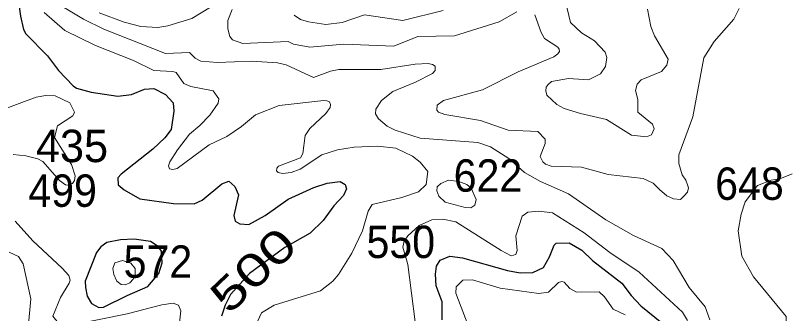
# Model space of a CAD drawing. Extents: x 499.9 to 555.3, y 9281.5 to 9336.8.
# Drawn here: x 535.43 to 539.258, y 9292.325 to 9293.797 of the extents above; entities that cross this region are included whole.
import ezdxf
from ezdxf.enums import TextEntityAlignment as Align

# ---------------------------------------------------------------- set-up
doc = ezdxf.new("R2010")
doc.units = 0
doc.header["$LTSCALE"] = 0.064
doc.layers.add('1', color=7, linetype='Continuous', lineweight=25)
doc.layers.add('2', color=7, linetype='Continuous', lineweight=13)
doc.layers.add('21', color=7, linetype='Continuous')
doc.layers.add('61', color=7, linetype='Continuous')

msp = doc.modelspace()

# ---------------------------------------------------------------- linework, layer by layer
at = {"layer": '1'}
for points in [[(535.4371, 9293.9261), (535.4546, 9293.7933), (535.4703, 9293.7273), (535.4808, 9293.7071), (535.5882, 9293.5975), (535.643, 9293.5252), (535.7149, 9293.4503), (535.7322, 9293.4378), (535.8042, 9293.4182), (535.936, 9293.3987), (536.0044, 9293.4069)], [(536.0044, 9293.4069), (536.0681, 9293.4335), (536.1149, 9293.4364), (536.1728, 9293.4068), (536.2106, 9293.3656), (536.2136, 9293.3253)], [(536.2136, 9293.3253), (536.2003, 9293.234), (536.1691, 9293.1933), (536.1103, 9293.1375), (535.9523, 9293.0129), (535.937, 9292.995), (535.9387, 9292.9606), (535.968, 9292.9357), (536.0458, 9292.8924), (536.2124, 9292.8678), (536.3131, 9292.8673), (536.3538, 9292.8846), (536.4503, 9292.965), (536.4858, 9292.9793), (536.5144, 9292.9528), (536.5333, 9292.9115), (536.5104, 9292.8092), (536.5171, 9292.7818), (536.5398, 9292.7679), (536.5836, 9292.7656), (536.665, 9292.8093), (536.7795, 9292.8896), (536.9053, 9292.9478), (536.9722, 9292.9689), (537.036, 9292.9764), (537.0605, 9292.9616), (537.0663, 9292.941), (537.0523, 9292.9084), (537.0042, 9292.8567), (536.9521, 9292.7843), (536.8869, 9292.7222), (536.7621, 9292.6508), (536.5877, 9292.523), (536.4932, 9292.4197), (536.4671, 9292.3664), (536.4487, 9292.3115)], [(537.5398, 9292.2948), (537.5408, 9292.3832), (537.511, 9292.4619), (537.5066, 9292.5203), (537.5113, 9292.5587), (537.5309, 9292.5886), (537.5781, 9292.6081), (537.6399, 9292.6011), (537.8635, 9292.5374), (537.9262, 9292.5265), (537.9879, 9292.5279), (538.0411, 9292.5527), (538.071, 9292.606), (538.0931, 9292.6624), (538.1032, 9292.6725), (538.1681, 9292.6741), (538.2311, 9292.6381), (538.2835, 9292.5863), (538.4284, 9292.4759), (538.4743, 9292.4144), (538.5232, 9292.3625), (538.6265, 9292.2787)]]:
    msp.add_lwpolyline(points, dxfattribs=at)
msp.add_lwpolyline([(536.0853, 9292.4582), (536.1398, 9292.523), (536.1553, 9292.5759), (536.152, 9292.6327), (536.1358, 9292.6561), (536.0979, 9292.6809), (536.0171, 9292.6922), (535.9503, 9292.6893), (535.882, 9292.6757), (535.8522, 9292.6549), (535.8308, 9292.6271), (535.7755, 9292.4847), (535.777, 9292.4533), (535.7846, 9292.4107), (535.806, 9292.3751), (535.8431, 9292.3549), (535.8652, 9292.3562), (535.9833, 9292.4146)], close=True, dxfattribs=at)
at = {"layer": '2'}
for points in [[(538.1747, 9293.7616), (538.1398, 9293.9095)], [(537.3081, 9293.2302), (537.269, 9293.2506), (537.2251, 9293.2866), (537.2104, 9293.3114), (537.2117, 9293.3342), (537.2401, 9293.3775), (537.296, 9293.4223), (537.409, 9293.4678), (537.4921, 9293.5109), (537.5057, 9293.526), (537.505, 9293.5466), (537.4925, 9293.5557), (537.4711, 9293.5591), (537.4067, 9293.556), (537.2363, 9293.5307), (537.0294, 9293.5307), (536.9873, 9293.5226), (536.9045, 9293.4912), (536.7683, 9293.5526), (536.7254, 9293.5625), (536.5975, 9293.572), (536.4295, 9293.5641), (536.3475, 9293.5721), (536.3187, 9293.5863), (536.2909, 9293.6149), (536.1716, 9293.609), (535.8671, 9293.7286), (535.7666, 9293.7796), (535.5814, 9293.8904)], [(535.8446, 9293.8095), (535.9686, 9293.7646), (536.0507, 9293.7425), (536.1341, 9293.7376), (536.1842, 9293.7462), (536.3021, 9293.7819), (536.4789, 9293.8914)], [(536.5011, 9293.8265), (536.4811, 9293.7724), (536.48, 9293.7311), (536.4908, 9293.6932), (536.5036, 9293.6772), (536.5544, 9293.6581), (536.778, 9293.6693), (536.8044, 9293.6559), (536.8853, 9293.6405), (537.0533, 9293.6548), (537.3016, 9293.6453), (537.4205, 9293.6933), (537.6016, 9293.6965), (537.8227, 9293.7655), (537.9095, 9293.8156)], [(537.545, 9293.8222), (537.3451, 9293.7727), (537.156, 9293.801), (537.046, 9293.7626), (536.9642, 9293.7519), (536.879, 9293.7656), (536.8402, 9293.7778), (536.8089, 9293.7987)], [(537.9985, 9293.7996), (538.0297, 9293.7131), (538.0454, 9293.6827), (538.1126, 9293.6413), (538.1186, 9293.6306), (538.1197, 9293.6191), (538.1126, 9293.6076), (538.0915, 9293.592), (537.916, 9293.5192), (537.7401, 9293.4296), (537.5463, 9293.3771), (537.5157, 9293.3546), (537.5143, 9293.3295), (537.5227, 9293.3203), (537.5539, 9293.3079), (537.7303, 9293.278), (537.8658, 9293.2315), (538.0137, 9293.2248), (538.0502, 9293.1862), (538.0499, 9293.1655), (538.0253, 9293.101), (538.0385, 9293.0738), (538.0511, 9293.0625), (538.0795, 9293.0529), (538.2294, 9293.0482), (538.3605, 9293.0122), (538.5342, 9292.9926), (538.5836, 9292.9686), (538.6149, 9292.9383), (538.6504, 9292.9072), (538.6839, 9292.8912), (538.719, 9292.8889), (538.7373, 9292.9057), (538.7535, 9292.9247), (538.7587, 9292.9461), (538.7534, 9292.9606), (538.7446, 9292.9842), (538.7275, 9293.0109), (538.7095, 9293.0668), (538.71, 9293.1088), (538.7793, 9293.2967), (538.8335, 9293.5878), (538.8848, 9293.6693), (538.9819, 9293.7791), (539.0085, 9293.8322)], [(538.5551, 9293.8276), (538.5725, 9293.7424), (538.5904, 9293.6972), (538.658, 9293.5815), (538.6518, 9293.5515), (538.6253, 9293.5202), (538.5247, 9293.4795), (538.5042, 9293.4573), (538.4967, 9293.4269), (538.5077, 9293.3829), (538.5077, 9293.3202), (538.5801, 9293.26), (538.588, 9293.2372), (538.5753, 9293.2077), (538.5499, 9293.198), (538.4763, 9293.2063), (538.3521, 9293.2841), (538.2247, 9293.3128), (538.1428, 9293.3381), (538.1077, 9293.3572), (538.0571, 9293.4039), (538.0523, 9293.4257), (538.054, 9293.443), (538.0647, 9293.4566), (538.0815, 9293.4702), (538.165, 9293.486), (538.2637, 9293.48), (538.323, 9293.5082), (538.3477, 9293.545)], [(535.5717, 9293.8125), (535.6742, 9293.7234), (535.8262, 9293.6481), (536.0136, 9293.5746), (536.1143, 9293.5248), (536.2087, 9293.5211), (536.2251, 9293.5152), (536.2623, 9293.4604), (536.2966, 9293.4459), (536.4071, 9293.4241), (536.4356, 9293.3853), (536.4331, 9293.3636), (536.3909, 9293.3053), (536.342, 9293.2532), (536.2913, 9293.2117), (536.2312, 9293.1343), (536.1936, 9293.0746), (536.1874, 9293.055), (536.1923, 9293.0405), (536.208, 9293.036), (536.2303, 9293.0411), (536.3884, 9293.1586), (536.4754, 9293.2001), (536.5473, 9293.2485), (536.6179, 9293.3069), (536.7334, 9293.3525), (536.9554, 9293.3777), (536.9697, 9293.3759), (536.9835, 9293.3711), (536.9875, 9293.3567), (536.9866, 9293.3423), (536.9655, 9293.3132), (536.8865, 9293.2387), (536.862, 9293.2049), (536.8518, 9293.1155), (536.8391, 9293.0942), (536.7309, 9293.0523), (536.7221, 9293.0433)], [(538.3477, 9293.545), (538.354, 9293.5892), (538.3462, 9293.6166), (538.2938, 9293.6722), (538.2287, 9293.7118), (538.1747, 9293.7616)], [(535.3495, 9293.3268), (535.5333, 9293.3939), (535.5803, 9293.4016), (535.6272, 9293.4001), (535.6984, 9293.366), (535.7228, 9293.3192), (535.7133, 9293.3012), (535.6378, 9293.252), (535.6233, 9293.1945), (535.7072, 9293.0618), (535.7247, 9293.0056), (535.7224, 9292.9819), (535.712, 9292.9678), (535.69, 9292.9599), (535.6783, 9292.9614), (535.6488, 9292.9817), (535.5659, 9293.0754), (535.5403, 9293.0897), (535.4816, 9293.1041), (535.4188, 9293.1104)], [(537.947, 9293.021), (537.8705, 9293.0913), (537.7799, 9293.1492), (537.717, 9293.17), (537.4311, 9293.1905), (537.3081, 9293.2302)], [(536.8373, 9293.0374), (536.9459, 9293.1089), (537.0223, 9293.1343), (537.1058, 9293.1471), (537.2204, 9293.1519), (537.3112, 9293.1424), (537.3939, 9293.1029), (537.4314, 9293.0719), (537.4687, 9293.0267), (537.4616, 9292.9617), (537.4232, 9292.926), (537.3413, 9292.8975), (537.1934, 9292.8642), (537.174, 9292.83), (537.1463, 9292.7333), (537.0936, 9292.6237), (537.0275, 9292.5186), (536.999, 9292.4849), (536.9388, 9292.4371), (536.7088, 9292.3662), (536.6472, 9292.3291), (536.6186, 9292.2683)], [(536.7221, 9293.0433), (536.7209, 9293.0307), (536.73, 9293.0215), (536.7508, 9293.0167), (536.7931, 9293.0209), (536.8373, 9293.0374)], [(538.8635, 9292.2941), (538.8397, 9292.3576), (538.7619, 9292.4533), (538.6822, 9292.5869), (538.627, 9292.6468), (538.4865, 9292.7111), (538.349, 9292.7882), (538.1649, 9292.9163), (538.0265, 9292.9776), (537.947, 9293.021)], [(538.9572, 9291.9867), (538.9844, 9292.0203), (539.0346, 9292.1486), (539.0659, 9292.1904), (539.0919, 9292.208), (539.1518, 9292.2134), (539.2143, 9292.2308), (539.2267, 9292.2424), (539.2405, 9292.2838), (539.2406, 9292.3114), (539.0791, 9292.506), (539.0214, 9292.6092), (539.0039, 9292.7341), (539.0179, 9292.8153), (539.0382, 9292.8762), (539.0992, 9292.9568), (539.1669, 9292.9844), (539.2097, 9292.9899), (539.2704, 9293.0156)], [(537.4061, 9292.2838), (537.3702, 9292.5669), (537.3458, 9292.6524), (537.3526, 9292.682), (537.3708, 9292.7083), (537.4267, 9292.7597), (537.4894, 9292.7875), (537.543, 9292.7918), (537.6069, 9292.7784), (537.8311, 9292.636), (537.8821, 9292.6103), (537.9037, 9292.6164), (537.911, 9292.6371), (537.9044, 9292.7085), (537.9363, 9292.8057), (537.9635, 9292.8253), (538.0177, 9292.8308), (538.086, 9292.8217), (538.2423, 9292.7242), (538.3687, 9292.6272), (538.5145, 9292.53), (538.7283, 9292.3321), (538.7539, 9292.2902)], [(535.4281, 9292.782), (535.5165, 9292.6849), (535.6607, 9292.5491), (535.6936, 9292.5127), (535.7001, 9292.4895), (535.6958, 9292.4745), (535.653, 9292.4042), (535.6148, 9292.3124), (535.6433, 9292.2776), (535.7148, 9292.2689), (535.9824, 9292.3237), (536.1541, 9292.3689), (536.2097, 9292.3766), (536.2368, 9292.3673), (536.2485, 9292.3385), (536.2328, 9292.205), (536.218, 9292.1515), (536.1382, 9292.0344), (536.1186, 9291.9829), (536.1059, 9291.9126), (536.1184, 9291.8739)], [(535.4244, 9292.1777), (535.4719, 9292.2178), (535.4938, 9292.2552), (535.5068, 9292.3983), (535.4678, 9292.5702), (535.4452, 9292.6062), (535.3996, 9292.6283)], [(537.6681, 9292.2662), (537.608, 9292.4253), (537.6087, 9292.4568), (537.6424, 9292.4905), (537.6907, 9292.4912), (537.8268, 9292.4501), (538.0178, 9292.4247), (538.0662, 9292.4313), (538.1152, 9292.4784), (538.1319, 9292.4832), (538.1439, 9292.4804), (538.1715, 9292.4485), (538.2048, 9292.4311), (538.316, 9292.4321), (538.3436, 9292.4079), (538.3853, 9292.346), (538.4457, 9292.3189)]]:
    msp.add_lwpolyline(points, dxfattribs=at)
for points in [[(537.5718, 9292.984), (537.5339, 9292.9668), (537.516, 9292.9502), (537.5139, 9292.9316), (537.5236, 9292.9047), (537.5546, 9292.8757), (537.6546, 9292.8482), (537.6815, 9292.8468), (537.7012, 9292.8604), (537.709, 9292.8882), (537.6835, 9292.944), (537.6622, 9292.9619), (537.6222, 9292.9778)], [(535.9214, 9292.5761), (535.9594, 9292.5878), (536.0013, 9292.5741), (536.0218, 9292.5478), (536.0218, 9292.5147), (536.012, 9292.4952), (535.9954, 9292.4767), (535.973, 9292.4669), (535.9525, 9292.4679), (535.9321, 9292.4854), (535.9175, 9292.5176), (535.9116, 9292.5478)]]:
    msp.add_lwpolyline(points, close=True, dxfattribs=at)

# ---------------------------------------------------------------- texts
at = {"layer": '21'}
msp.add_text('435', height=0.16, dxfattribs=at).set_placement((535.5312, 9293.0729))
at = {"layer": '21', "width": 0.95}
for s, p in [('622', (537.597, 9292.9268)), ('648', (538.8899, 9292.8866)), ('499', (535.4939, 9292.8521)), ('550', (537.166, 9292.5992)), ('572', (535.965, 9292.5016))]:
    msp.add_text(s, height=0.16, dxfattribs=at).set_placement(p)
at = {"layer": '61', "width": 1.35}
msp.add_text('500', height=0.16, rotation=43.603, dxfattribs=at).set_placement((536.6609, 9292.4822), align=Align.CENTER)

doc.saveas('drawing.dxf')
